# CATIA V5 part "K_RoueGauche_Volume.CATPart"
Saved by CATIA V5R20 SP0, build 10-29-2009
Part number: roue_gauche_volume
Publications: "Corps principal"
Bounding box of the stored display mesh (mm): x -199.964 to 199.964, y 553.75 to 633.75, z -199.97 to 199.97
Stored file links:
  G:\Khaled_CFAO_2011\ST2M\ST2M_GR1\cdurantin\cdurantin\Khaled\CAD_ThinkMOTION\K_RoueGauche_Volume.CATPart
  C:\Documents and Settings\cdurantin\Bureau\cdurantin\caddy.CATProduct
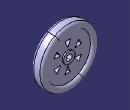
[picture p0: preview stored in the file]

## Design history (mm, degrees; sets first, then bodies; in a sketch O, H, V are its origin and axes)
Parameters
  diam_ext = 400 mm
  epaisseur_pneu = 40 mm
External parameters (linked from other documents)
  `External.diamètre des barres` = 40 mm
  `External.Surepaisseur du tube` = 10 mm
  `External.largeur pivot` = 125 mm
  `External.largeur de la glissière` = 100 mm
  `External.Longueur de barres du corps` = 800 mm
Set1
  DatumSurface1: linked copy from another document
  Line1: linked copy from another document
Body1 (main body)
  Sketch1 on yz-plane, origin (0, 0, 0), H (0, 1, 0), V (0, 0, 1)
    arc A1 centre (593.75, 0) radius 200 from (615.9722, 198.7616) to (571.5278, 198.7616) ccw
    point P1 (593.75, 0)
    arc A2 centre (613.75, 178.8854) radius 20 from (613.75, 158.8854) to (615.9722, 198.7616) ccw
    point P2 (613.75, 178.8854)
    arc A3 centre (573.75, 178.8854) radius 20 from (571.5278, 198.7616) to (573.75, 158.8854) ccw
    point P3 (573.75, 178.8854)
    line L1 (563.75, 20) -> (623.75, 20)
    line L2 (623.75, 20) -> (623.75, 40)
    line L3 (623.75, 40) -> (613.75, 40)
    line L4 (613.75, 40) -> (613.75, 158.8854)
    line L5 (563.75, 20) -> (563.75, 40)
    point P9 (563.75, 40)
    line L6 (563.75, 40) -> (573.75, 40)
    line L7 (573.75, 40) -> (573.75, 158.8854)
    radius A1 = 200 {= diam_ext /2}
    distance P1 H = 0
    distance P1 V = 593.75 {= `External.Longueur de barres du corps` /2+`External.largeur de la glissière` +3*`External.largeur pivot` /4}
    radius A2 = 20 {= epaisseur_pneu /2}
    radius A3 = 20 {= epaisseur_pneu /2}
    distance P2 P3 = 40 {= epaisseur_pneu}
    distance L7 P3 = 0
    distance L4 P2 = 0
    length L2 = 20 {= 2*`External.Surepaisseur du tube`}
    distance L1 H = 20 {= `External.diamètre des barres` /2}
    distance L4 P1 = 20 {= epaisseur_pneu /2}
    distance L2 L4 = 10 {= `External.Surepaisseur du tube`}
    distance L7 L5 = 10 {= `External.Surepaisseur du tube`}
    tangency: A2 A1, A3 A1
    horizontal: L1 H, L3 H, L6 H
    vertical: L2 V, L4 V, L7 V
    coincidence: P9 L3
  Shaft1: profile Sketch1, axis Sketch1.H, angle 360
  Sketch2 on face of Shaft1 from Sketch1.L4, origin (0, 613.75, 0), H (-1, 0, 0), V (0, 0, 1)
    line L1 (-20, 100) -> (20, 100)
    line L2 (20, 100) -> (0, 57.1099)
    point P3 (0, 57.1099)
    line L3 (0, 57.1099) -> (-20, 100)
    length L1 = 40 {= epaisseur_pneu}
    angle L1 L2 = 115
    angle L3 L1 = 115
    distance L1 H = 100 {= diam_ext /4}
    horizontal: L1 H
    coincidence: P3 V
  Pocket1: profile Sketch2, direction (0, -1, 0), through (limit type 6)
  CircPattern1: of Pocket1, instances 6, angular step 60, axis from Line1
